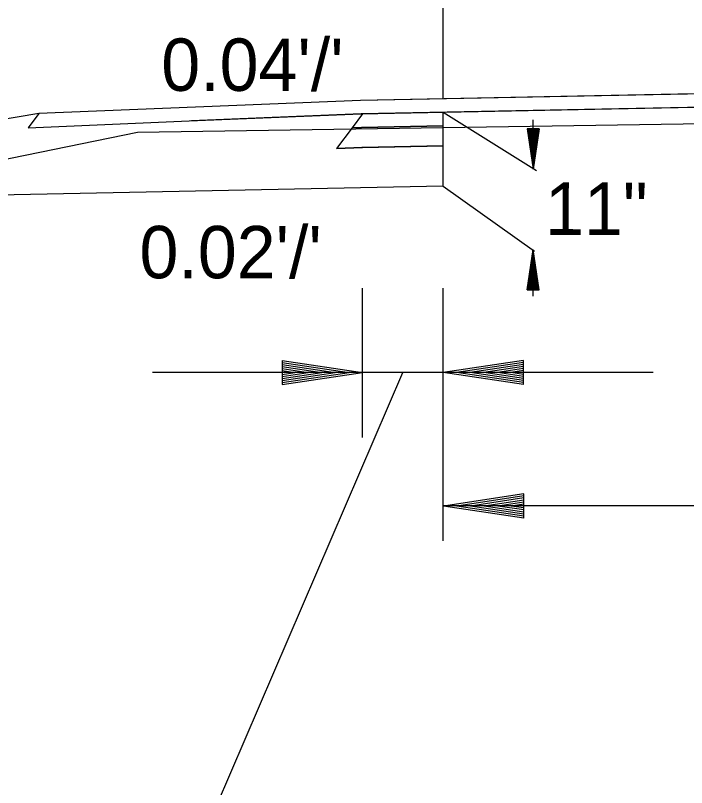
# Model space of a CAD drawing. Extents: x 6848689 to 6848907, y 1900908 to 1901005.
# Drawn here: x 6848730.81 to 6848739.15, y 1900919.73 to 1900929.32 of the extents above; entities that cross this region are included whole.
import ezdxf

# ---------------------------------------------------------------- set-up
doc = ezdxf.new("R2010")
doc.units = 0
for name, color, linetype in [('Default', 7, 'Continuous'), ('R_Draft', 7, 'Continuous'), ('R_No Plot', 7, 'Continuous')]:
    doc.layers.add(name, color=color, linetype=linetype)

msp = doc.modelspace()

# ---------------------------------------------------------------- linework, layer by layer
at = {"layer": 'Default'}
for p, q in [((6848746.0972, 1900928.4819), (6848735.0994, 1900928.2619)), ((6848746.0972, 1900928.3151), (6848735.106, 1900928.0954)), ((6848735.0994, 1900928.2619), (6848731.1026, 1900928.102)), ((6848731.1026, 1900928.102), (6848721.0972, 1900926.4346)), ((6848732.3297, 1900927.8687), (6848746.123, 1900928.0822)), ((6848735.106, 1900928.0954), (6848732.999, 1900928.0111)), ((6848735.124, 1900928.0957), (6848734.995, 1900927.9238)), ((6848736.124, 1900927.949), (6848736.124, 1900928.1157)), ((6848735.1126, 1900927.9288), (6848734.995, 1900927.9238)), ((6848736.124, 1900927.949), (6848735.1093, 1900927.9287)), ((6848736.124, 1900927.699), (6848736.124, 1900927.949)), ((6848726.3295, 1900926.6484), (6848732.3297, 1900927.8687)), ((6848734.995, 1900927.9238), (6848734.8016, 1900927.6658)), ((6848735.1226, 1900927.679), (6848734.8016, 1900927.6658)), ((6848736.124, 1900927.699), (6848735.1143, 1900927.6788)), ((6848736.124, 1900927.1988), (6848724.2587, 1900926.9615))]:
    msp.add_line(p, q, dxfattribs=at)
for points in [[(6848746.0972, 1900928.4819), (6848735.0994, 1900928.2619), (6848731.1026, 1900928.102), (6848730.9696, 1900927.9247), (6848732.9702, 1900928.0099), (6848735.106, 1900928.0954), (6848746.0972, 1900928.3151)], [(6848736.124, 1900928.1157), (6848735.124, 1900928.0957), (6848735.124, 1900928.0957), (6848734.995, 1900927.9238), (6848735.1126, 1900927.9288), (6848736.124, 1900927.949)], [(6848736.124, 1900927.949), (6848735.1126, 1900927.9288), (6848734.995, 1900927.9238)], [(6848734.995, 1900927.9238), (6848734.8016, 1900927.6658), (6848735.1226, 1900927.679), (6848736.124, 1900927.699)]]:
    msp.add_lwpolyline(points, dxfattribs=at)
at = {"layer": 'R_Draft'}
for p, q in [((6848737.2424, 1900927.41), (6848737.2424, 1900928.0229)), ((6848737.1674, 1900927.91), (6848737.2424, 1900927.41)), ((6848737.3174, 1900927.91), (6848737.1674, 1900927.91)), ((6848737.1799, 1900927.91), (6848737.2424, 1900927.4935)), ((6848737.1926, 1900927.91), (6848737.2424, 1900927.5795)), ((6848737.2051, 1900927.91), (6848737.2424, 1900927.6628)), ((6848737.2179, 1900927.91), (6848737.2424, 1900927.7475)), ((6848737.2306, 1900927.91), (6848737.2424, 1900927.831)), ((6848737.3174, 1900927.91), (6848737.2424, 1900927.41)), ((6848737.2666, 1900927.91), (6848737.2424, 1900927.7475)), ((6848737.2921, 1900927.91), (6848737.2424, 1900927.5795)), ((6848737.3049, 1900927.91), (6848737.2424, 1900927.4935)), ((6848737.2796, 1900927.91), (6848737.2424, 1900927.6628)), ((6848737.2541, 1900927.91), (6848737.2424, 1900927.831)), ((6848737.1674, 1900925.912), (6848737.2424, 1900926.412)), ((6848737.2424, 1900925.8332), (6848737.2424, 1900926.412)), ((6848737.3174, 1900925.912), (6848737.2424, 1900926.412)), ((6848737.1799, 1900925.912), (6848737.2424, 1900926.3285)), ((6848737.3049, 1900925.912), (6848737.2424, 1900926.3285)), ((6848737.1926, 1900925.912), (6848737.2424, 1900926.2425)), ((6848737.2921, 1900925.912), (6848737.2424, 1900926.2425)), ((6848737.2051, 1900925.912), (6848737.2424, 1900926.1593)), ((6848737.2796, 1900925.912), (6848737.2424, 1900926.1593)), ((6848737.2181, 1900925.912), (6848737.2424, 1900926.0745)), ((6848737.2669, 1900925.912), (6848737.2424, 1900926.0745)), ((6848737.1674, 1900925.912), (6848737.3174, 1900925.912)), ((6848737.2306, 1900925.912), (6848737.2424, 1900925.991)), ((6848737.2541, 1900925.912), (6848737.2424, 1900925.991)), ((6848734.124, 1900925.0366), (6848735.124, 1900924.8866)), ((6848734.124, 1900925.0366), (6848734.124, 1900924.7366)), ((6848734.124, 1900925.0116), (6848734.957, 1900924.8866)), ((6848734.124, 1900924.9861), (6848734.785, 1900924.8866)), ((6848734.124, 1900924.9611), (6848734.6185, 1900924.8866)), ((6848737.124, 1900925.0366), (6848736.124, 1900924.8866)), ((6848737.124, 1900925.0116), (6848736.291, 1900924.8866)), ((6848737.124, 1900924.9861), (6848736.463, 1900924.8866)), ((6848737.124, 1900924.9611), (6848736.6295, 1900924.8866)), ((6848737.124, 1900924.7366), (6848737.124, 1900925.0366)), ((6848732.1954, 1900916.9155), (6848735.624, 1900924.8866)), ((6848734.124, 1900924.9351), (6848734.449, 1900924.8866)), ((6848734.124, 1900924.9101), (6848734.282, 1900924.8866)), ((6848734.124, 1900924.7366), (6848735.124, 1900924.8866)), ((6848734.124, 1900924.8376), (6848734.449, 1900924.8866)), ((6848734.124, 1900924.7871), (6848734.785, 1900924.8866)), ((6848734.124, 1900924.7616), (6848734.957, 1900924.8866)), ((6848734.124, 1900924.8121), (6848734.6185, 1900924.8866)), ((6848734.124, 1900924.8631), (6848734.282, 1900924.8866)), ((6848736.124, 1900924.8866), (6848735.124, 1900924.8866)), ((6848737.124, 1900924.7366), (6848736.124, 1900924.8866)), ((6848737.124, 1900924.7616), (6848736.291, 1900924.8866)), ((6848737.124, 1900924.7871), (6848736.463, 1900924.8866)), ((6848737.124, 1900924.8121), (6848736.6295, 1900924.8866)), ((6848737.124, 1900924.9356), (6848736.799, 1900924.8866)), ((6848737.124, 1900924.8381), (6848736.799, 1900924.8866)), ((6848737.124, 1900924.9101), (6848736.966, 1900924.8866)), ((6848737.124, 1900924.8631), (6848736.966, 1900924.8866)), ((6848737.1277, 1900923.3795), (6848736.1277, 1900923.2295)), ((6848737.1277, 1900923.3545), (6848736.2947, 1900923.2295)), ((6848737.1277, 1900923.329), (6848736.4667, 1900923.2295)), ((6848737.1277, 1900923.0795), (6848737.1277, 1900923.3795)), ((6848737.1277, 1900923.0795), (6848736.1277, 1900923.2295)), ((6848737.1277, 1900923.1045), (6848736.2947, 1900923.2295)), ((6848737.1277, 1900923.13), (6848736.4667, 1900923.2295)), ((6848737.1277, 1900923.304), (6848736.6332, 1900923.2295)), ((6848737.1277, 1900923.155), (6848736.6332, 1900923.2295)), ((6848737.1277, 1900923.2785), (6848736.8027, 1900923.2295)), ((6848737.1277, 1900923.181), (6848736.8027, 1900923.2295)), ((6848737.1277, 1900923.253), (6848736.9697, 1900923.2295)), ((6848737.1277, 1900923.206), (6848736.9697, 1900923.2295))]:
    msp.add_line(p, q, dxfattribs=at)
at = {"layer": 'R_No Plot'}
for p, q in [((6848736.124, 1900928.2824), (6848736.124, 1900931.7162)), ((6848736.124, 1900928.1161), (6848737.2842, 1900927.3927)), ((6848736.124, 1900927.1988), (6848737.262, 1900926.3929)), ((6848735.124, 1900924.0791), (6848735.124, 1900925.9329)), ((6848735.124, 1900924.8866), (6848732.514, 1900924.8866)), ((6848738.734, 1900924.8866), (6848736.124, 1900924.8866)), ((6848756.124, 1900923.2314), (6848736.124, 1900923.2314))]:
    msp.add_line(p, q, dxfattribs=at)
for points in [[(6848736.124, 1900927.1988), (6848736.124, 1900928.1157)], [(6848736.124, 1900922.7978), (6848736.124, 1900925.9329)]]:
    msp.add_lwpolyline(points, dxfattribs=at)

# ---------------------------------------------------------------- texts
at = {"layer": 'R_Draft'}
for s, p in [("0.04'/'", (6848732.6238, 1900928.3827)), ('11"', (6848737.391, 1900926.5952)), ("0.02'/'", (6848732.3531, 1900926.0561))]:
    msp.add_text(s, height=0.65, rotation=359.98, dxfattribs=at).set_placement(p)

doc.saveas('drawing.dxf')
